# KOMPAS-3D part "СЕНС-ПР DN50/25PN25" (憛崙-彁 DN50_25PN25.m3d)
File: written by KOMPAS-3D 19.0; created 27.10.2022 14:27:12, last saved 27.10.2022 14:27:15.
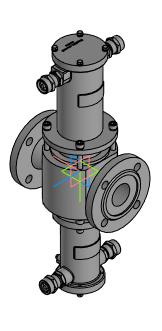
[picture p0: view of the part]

Document properties: Автор: setup; Полное имя файла: .

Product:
- Part/product: СЕНС-ПР DN50/25PN25
    Масса: 25.93
  - Body: Тело 1
      Масса: 29.0908

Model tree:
1. Операция без истории:1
